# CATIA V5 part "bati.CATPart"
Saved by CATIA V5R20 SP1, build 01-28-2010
Part number: bati
Bounding box of the stored display mesh (mm): x -563 to 487, y -50 to 425, z -20 to 0
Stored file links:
  D:\Dropbox\IAO_2011\MMS_GR1\jdubreuilr\jdubreuilr\jdubreuilr\bati.CATPart
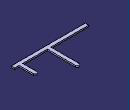
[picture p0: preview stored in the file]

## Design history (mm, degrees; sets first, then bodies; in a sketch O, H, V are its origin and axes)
Set1
  Point1: (0, 0, 0)
  Point2: (400, 200, 0)
  Point3: (0, 400, 0)
  Line1: type Normal, RefPoint Point3, RefSkin start face of Pad1, Start 0, End 20
  Line2: type Normal, RefPoint Point2, RefSkin start face of Pad1, Start 0, End 20
Body1 (main body)
  Sketch1 on xy-plane, origin (0, 0, 0), H (1, 0, 0), V (0, 1, 0)
    line L1 (-563, 0) -> (-563, -50)
    point P2 (-563, -50)
    line L2 (487, 0) -> (487, -50)
    line L3 (487, -50) -> (-563, -50)
    point P5 (-563, -50)
    line L4 (-563, 0) -> (-25, 0)
    line L5 (-25, 0) -> (-25, 400)
    point P7 (-25, 400)
    line L6 (25, 400) -> (25, 0)
    point P8 (25, 0)
    point P9 (25, 400)
    line L7 (25, 0) -> (375, 0)
    line L8 (375, 0) -> (375, 200)
    line L9 (425, 200) -> (425, 0)
    point P12 (425, 0)
    point P13 (425, 200)
    line L10 (425, 0) -> (487, 0)
    arc A1 centre (0, 400) radius 25 from (25, 400) to (-25, 400) ccw
    point P14 (0, 400)
    point P15 (-25, 400)
    point P16 (25, 400)
    arc A2 centre (400, 200) radius 25 from (425, 200) to (375, 200) ccw
    point P18 (425, 200)
    length L3 = 1050
    distance L5 L6 = 50
    distance L5 V = 25
    distance L9 L8 = 50
    distance L8 V = 375
    length L9 = 200
    length L8 = 200
    length L6 = 400
    length L5 = 400
    distance P14 O = 400
    distance L3 L7 = 50
    vertical: L1 V, L2 V, L5 V, L6 V, L8 V, L9 V
    horizontal: L3 H, L4 H, L7 H, L10 H
    coincidence: P5 P2, P8 L4, P12 L7, P15 L5, P16 L6, P16 P9, L4 H, P15 P7, P18 L9, P18 P13
    tangency: A2 L8
  Pad1: profile Sketch1, direction (0, 0, -1), length 20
